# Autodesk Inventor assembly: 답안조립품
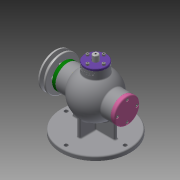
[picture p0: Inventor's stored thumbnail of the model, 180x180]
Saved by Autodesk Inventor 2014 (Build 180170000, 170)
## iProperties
Created: 2020-08
Part Number: 답안조립품
Document SubType Name: Assembly
Designer: kh
Author: kh
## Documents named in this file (18)
- C:\Users\kh\Desktop\700806V1027\답안조립품.iam
- C:\Users\kh\Desktop\700806V1027\본체.ipt
- C:\Users\kh\Desktop\700806V1027\V-벨트풀리.ipt
- C:\Users\kh\Desktop\700806V1027\너트 M8.ipt
- C:\Users\kh\Desktop\700806V1027\뒤커버.ipt
- C:\Users\kh\Desktop\700806V1027\멈춤링 15x1.ipt
- C:\Users\kh\Desktop\700806V1027\멈춤링 35x1.6.ipt
- 멈춤링 35x1.6.ipt
- C:\Users\kh\Desktop\700806V1027\베어링 6202.ipt
- 베어링 6202.ipt
- C:\Users\kh\Desktop\700806V1027\볼트 M4.ipt
- C:\Users\kh\Desktop\700806V1027\상부커버.ipt
- C:\Users\kh\Desktop\700806V1027\슬라이드.ipt
- C:\Users\kh\Desktop\700806V1027\앞커버.ipt
- C:\Users\kh\Desktop\700806V1027\오일 실 15 30 7.ipt
- C:\Users\kh\Desktop\700806V1027\칼라.ipt
- C:\Users\kh\Desktop\700806V1027\키 3x3x12.ipt
- C:\Users\kh\Desktop\700806V1027\편심축.ipt
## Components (1 placed, 1 different names)
1. V-벨트풀리:1 — Insert:12, Mate:14, Insert:13
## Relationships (3: Insert 2, Mate 1)
- Insert:12: V-벨트풀리:1
- Mate:14: V-벨트풀리:1
- Insert:13: V-벨트풀리:1
